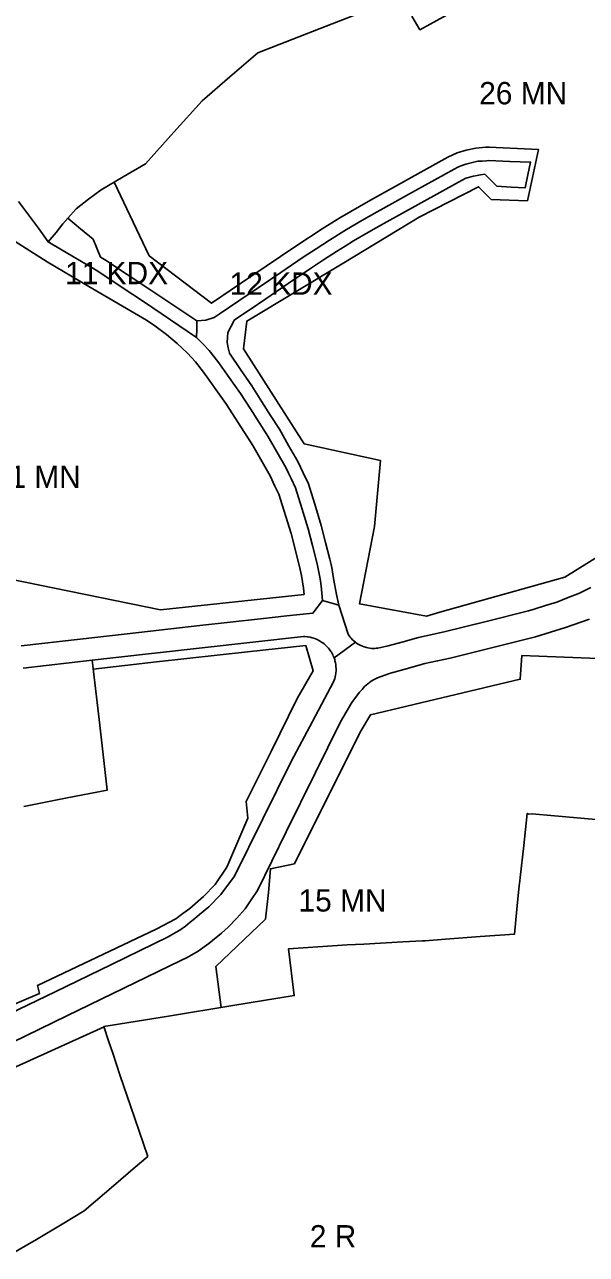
# Model space of a CAD drawing. Extents: x 7423432 to 7425824, y 5537848 to 5539677.
# Drawn here: x 7425211 to 7425463, y 5538662 to 5539213 of the extents above; entities that cross this region are included whole.
import ezdxf

# ---------------------------------------------------------------- set-up
doc = ezdxf.new("R2010")
doc.units = 0
for name, color, linetype in [('linie_rozgraniczajace', 7, 'Continuous'), ('linie_zabudowy_nieprzekraczalne', 7, 'Continuous'), ('oznaczenia_przeznaczen', 7, 'Continuous')]:
    doc.layers.add(name, color=color, linetype=linetype)

msp = doc.modelspace()

# ---------------------------------------------------------------- linework, layer by layer
at = {"layer": 'linie_rozgraniczajace'}
for points in [[(7425371.35, 5539221.95), (7425343.4, 5539211.07), (7425315.44, 5539200.19), (7425302.99, 5539189.48), (7425290.54, 5539178.76), (7425277.84, 5539164.59), (7425265.13, 5539150.42), (7425255.24, 5539144.66), (7425245.36, 5539138.9), (7425239.75, 5539134.64), (7425234.14, 5539130.39), (7425230.38, 5539126.15), (7425228.2, 5539123.69), (7425225.18, 5539119.76), (7425221.59, 5539115.58), (7425217.25, 5539121.7), (7425212.82, 5539127.69), (7425208.39, 5539133.68)], [(7425230.38, 5539126.15), (7425234.14, 5539130.39), (7425239.75, 5539134.64), (7425245.36, 5539138.9), (7425255.24, 5539144.66), (7425265.13, 5539150.42), (7425277.84, 5539164.59), (7425290.54, 5539178.76), (7425302.99, 5539189.48), (7425315.44, 5539200.19), (7425343.4, 5539211.07), (7425371.35, 5539221.95)], [(7425384.41, 5539216.52), (7425388.03, 5539210.53), (7425400.21, 5539217.11)], [(7425400.21, 5539217.11), (7425388.03, 5539210.53), (7425384.41, 5539216.52)], [(7425418.91, 5539151.93), (7425417.8, 5539151.9), (7425415.87, 5539151.76), (7425413.93, 5539151.62), (7425412.1, 5539151.2), (7425408.54, 5539150.29), (7425406.81, 5539149.8), (7425405.05, 5539148.96), (7425403.3, 5539148.12), (7425386.09, 5539138.56), (7425368.88, 5539129), (7425362.03, 5539125.07), (7425355.19, 5539121.15), (7425347.5, 5539116.34), (7425341.61, 5539112.52), (7425335.73, 5539108.7), (7425325.7, 5539101.88), (7425315.67, 5539095.07), (7425306.9, 5539089.11), (7425298.13, 5539083.14), (7425295.98, 5539081.68), (7425292.19, 5539080.59), (7425288.16, 5539080.16), (7425267.53, 5539093.92), (7425246.9, 5539107.68), (7425245.11, 5539108.69), (7425241.79, 5539116.75), (7425236.09, 5539121.45), (7425230.38, 5539126.15)], [(7425288.09, 5539072.74), (7425288.13, 5539076.45), (7425288.16, 5539080.16), (7425292.19, 5539080.59), (7425295.98, 5539081.68), (7425298.13, 5539083.14), (7425306.9, 5539089.11), (7425315.67, 5539095.07), (7425325.7, 5539101.88), (7425335.73, 5539108.7), (7425341.61, 5539112.52), (7425347.5, 5539116.34), (7425355.19, 5539121.15), (7425362.03, 5539125.07), (7425368.88, 5539129), (7425386.09, 5539138.56), (7425403.3, 5539148.12), (7425405.05, 5539148.96), (7425406.81, 5539149.8), (7425408.54, 5539150.29), (7425412.1, 5539151.2), (7425413.93, 5539151.62), (7425415.87, 5539151.76), (7425417.8, 5539151.9), (7425418.91, 5539151.93), (7425428.23, 5539151.6), (7425437.55, 5539151.28), (7425436.35, 5539145.52), (7425435.15, 5539139.76), (7425428.8, 5539140.11), (7425422.45, 5539140.46), (7425420.05, 5539142.86), (7425417.11, 5539145.82), (7425415.18, 5539145.64), (7425413.62, 5539145.32), (7425412.06, 5539145), (7425408.61, 5539144.01), (7425405.23, 5539142.3), (7425388.51, 5539133.03), (7425371.79, 5539123.75), (7425365.03, 5539119.88), (7425358.27, 5539116), (7425354.5, 5539113.64), (7425350.72, 5539111.28), (7425344.86, 5539107.47), (7425338.99, 5539103.67), (7425329.02, 5539096.89), (7425319.04, 5539090.11), (7425312.06, 5539085.37), (7425305.09, 5539080.63), (7425302.1, 5539075.02), (7425301.73, 5539070.48), (7425302.26, 5539068.14), (7425302.78, 5539065.79), (7425307.75, 5539058.45), (7425312.72, 5539051.1), (7425314.98, 5539047.57), (7425317.24, 5539044.03), (7425321.19, 5539037.86), (7425325.15, 5539031.69), (7425329.27, 5539024.49), (7425333.39, 5539017.3), (7425334.58, 5539014.78), (7425335.77, 5539012.27), (7425336.86, 5539009.98), (7425337.94, 5539007.69), (7425340.91, 5538998.18), (7425343.87, 5538988.67), (7425345.8, 5538981.08), (7425347.73, 5538973.5), (7425348.23, 5538971.2), (7425348.73, 5538968.89), (7425349.24, 5538965.74), (7425349.76, 5538962.58), (7425350.7, 5538957.77), (7425351.65, 5538952.97), (7425344.41, 5538955.04), (7425344.12, 5538958.35), (7425343.83, 5538961.65), (7425343.33, 5538964.71), (7425342.83, 5538967.77), (7425342.36, 5538969.95), (7425341.89, 5538972.13), (7425339.97, 5538979.66), (7425338.06, 5538987.19), (7425335.2, 5538996.35), (7425332.34, 5539005.5), (7425330.35, 5539009.7), (7425329.21, 5539012.11), (7425328.07, 5539014.52), (7425324.04, 5539021.55), (7425320.01, 5539028.58), (7425316.1, 5539034.69), (7425312.19, 5539040.8), (7425309.97, 5539044.27), (7425307.75, 5539047.74), (7425302.66, 5539054.85), (7425297.57, 5539061.97), (7425293.76, 5539067.01)], [(7425464.55, 5538960.86), (7425459.47, 5538958.37), (7425454.4, 5538956.38), (7425449.33, 5538954.39), (7425444.22, 5538952.81), (7425439.11, 5538951.23), (7425436.57, 5538950.44), (7425417.68, 5538945.72), (7425398.8, 5538940.99), (7425387.31, 5538938.48), (7425380.54, 5538936.63), (7425373.76, 5538934.77), (7425369.25, 5538933.77), (7425368.46, 5538933.68), (7425367.8, 5538933.63), (7425367.21, 5538933.62), (7425366.3, 5538933.65), (7425365.63, 5538933.72), (7425364.72, 5538933.86), (7425364.04, 5538934.01), (7425363.07, 5538934.29), (7425362.34, 5538934.56), (7425361.61, 5538934.87), (7425360.91, 5538935.22), (7425360.13, 5538935.68), (7425359.52, 5538936.09), (7425359.14, 5538936.37), (7425358.44, 5538936.95), (7425357.88, 5538937.47), (7425357.25, 5538938.15), (7425356.81, 5538938.67), (7425356.39, 5538939.22), (7425355.88, 5538940), (7425351.65, 5538952.97), (7425350.7, 5538957.77), (7425349.76, 5538962.58), (7425349.24, 5538965.74), (7425348.73, 5538968.89), (7425348.23, 5538971.2), (7425347.73, 5538973.5), (7425345.8, 5538981.08), (7425343.87, 5538988.67), (7425340.91, 5538998.18), (7425337.94, 5539007.69), (7425336.86, 5539009.98), (7425335.77, 5539012.27), (7425334.58, 5539014.78), (7425333.39, 5539017.3), (7425329.27, 5539024.49), (7425325.15, 5539031.69), (7425321.19, 5539037.86), (7425317.24, 5539044.03), (7425314.98, 5539047.57), (7425312.72, 5539051.1), (7425307.75, 5539058.45), (7425302.78, 5539065.79), (7425302.26, 5539068.14), (7425301.73, 5539070.48), (7425302.1, 5539075.02), (7425305.09, 5539080.63), (7425312.06, 5539085.37), (7425319.04, 5539090.11), (7425329.02, 5539096.89), (7425338.99, 5539103.67), (7425344.86, 5539107.47), (7425350.72, 5539111.28), (7425354.5, 5539113.64), (7425358.27, 5539116), (7425365.03, 5539119.88), (7425371.79, 5539123.75), (7425388.51, 5539133.03), (7425405.23, 5539142.3), (7425408.61, 5539144.01), (7425412.06, 5539145), (7425413.62, 5539145.32), (7425415.18, 5539145.64), (7425417.11, 5539145.82), (7425420.05, 5539142.86), (7425422.45, 5539140.46), (7425428.8, 5539140.11), (7425435.15, 5539139.76), (7425436.35, 5539145.52), (7425437.55, 5539151.28), (7425428.23, 5539151.6), (7425418.91, 5539151.93)], [(7425208.39, 5539133.68), (7425212.82, 5539127.69), (7425217.25, 5539121.7), (7425221.59, 5539115.58), (7425227.89, 5539111.88), (7425239.03, 5539105.34), (7425243.87, 5539102.5), (7425254.32, 5539095.51), (7425264.78, 5539088.53), (7425276.43, 5539080.63), (7425288.09, 5539072.74), (7425290.92, 5539069.88), (7425293.76, 5539067.01), (7425297.57, 5539061.97), (7425302.66, 5539054.85), (7425307.75, 5539047.74), (7425309.97, 5539044.27), (7425312.19, 5539040.8), (7425316.1, 5539034.69), (7425320.01, 5539028.58), (7425324.04, 5539021.55), (7425328.07, 5539014.52), (7425329.21, 5539012.11), (7425330.35, 5539009.7), (7425332.34, 5539005.5), (7425335.2, 5538996.35), (7425338.06, 5538987.19), (7425339.97, 5538979.66), (7425341.89, 5538972.13), (7425342.36, 5538969.95), (7425342.83, 5538967.77), (7425343.33, 5538964.71), (7425343.83, 5538961.65), (7425344.12, 5538958.35), (7425344.41, 5538955.04), (7425340.12, 5538949.43), (7425328.43, 5538948.16), (7425316.74, 5538946.9), (7425289.5, 5538943.82), (7425262.26, 5538940.75), (7425235.92, 5538937.77), (7425209.58, 5538934.8)], [(7425293.76, 5539067.01), (7425290.92, 5539069.88), (7425288.09, 5539072.74)], [(7425280.51, 5538807.61), (7425283.16, 5538809.39), (7425285.18, 5538811.05), (7425287.31, 5538812.8), (7425289.37, 5538814.56), (7425293.47, 5538818.05), (7425298.87, 5538823.46), (7425305, 5538831.65), (7425317.69, 5538857.37), (7425330.39, 5538883.09), (7425339.89, 5538900.85), (7425349.38, 5538918.62), (7425349.87, 5538920.19), (7425350.04, 5538920.81), (7425350.26, 5538921.8), (7425350.35, 5538922.37), (7425350.41, 5538922.89), (7425350.46, 5538923.46), (7425350.48, 5538924.02), (7425350.49, 5538924.67), (7425350.45, 5538925.38), (7425350.39, 5538926.03), (7425350.32, 5538926.6), (7425350.23, 5538927.11), (7425350.13, 5538927.59), (7425349.99, 5538928.14), (7425349.86, 5538928.61), (7425349.61, 5538929.35), (7425359.14, 5538936.37), (7425359.52, 5538936.09), (7425360.13, 5538935.68), (7425360.91, 5538935.22), (7425361.61, 5538934.87), (7425362.34, 5538934.56), (7425363.07, 5538934.29), (7425364.04, 5538934.01), (7425364.72, 5538933.86), (7425365.63, 5538933.72), (7425366.3, 5538933.65), (7425367.21, 5538933.62), (7425367.8, 5538933.63), (7425368.46, 5538933.68), (7425369.25, 5538933.77), (7425373.76, 5538934.77), (7425380.54, 5538936.63), (7425387.31, 5538938.48), (7425398.8, 5538940.99), (7425417.68, 5538945.72), (7425436.57, 5538950.44), (7425439.11, 5538951.23), (7425444.22, 5538952.81), (7425449.33, 5538954.39), (7425454.4, 5538956.38), (7425459.47, 5538958.37), (7425464.55, 5538960.86)], [(7425209.58, 5538934.8), (7425235.92, 5538937.77), (7425262.26, 5538940.75), (7425289.5, 5538943.82), (7425316.74, 5538946.9), (7425328.43, 5538948.16), (7425340.12, 5538949.43), (7425344.41, 5538955.04), (7425351.65, 5538952.97), (7425355.88, 5538940), (7425356.39, 5538939.22), (7425356.81, 5538938.67), (7425357.25, 5538938.15), (7425357.88, 5538937.47), (7425358.44, 5538936.95), (7425359.14, 5538936.37), (7425349.61, 5538929.35), (7425349.44, 5538929.79), (7425349.26, 5538930.22), (7425348.99, 5538930.8), (7425348.74, 5538931.28), (7425348.39, 5538931.89), (7425348.18, 5538932.24), (7425347.58, 5538933.09), (7425347.04, 5538933.77), (7425346.42, 5538934.46), (7425345.73, 5538935.13), (7425345.16, 5538935.62), (7425344.55, 5538936.09), (7425343.98, 5538936.48), (7425343.03, 5538937.06), (7425341.97, 5538937.6), (7425341.21, 5538937.92), (7425340.47, 5538938.18), (7425339.76, 5538938.39), (7425338.82, 5538938.61), (7425338.06, 5538938.75), (7425337.48, 5538938.82), (7425336.57, 5538938.89), (7425335.85, 5538938.9), (7425313.23, 5538936.39), (7425290.61, 5538933.88), (7425250.55, 5538929.36), (7425241.35, 5538928.32), (7425210.49, 5538924.84)], [(7425205.76, 5538757.48), (7425229.98, 5538769.16), (7425255.51, 5538781.54), (7425281.03, 5538793.93), (7425283.92, 5538795.37), (7425288.84, 5538798.14), (7425293.5, 5538801.54), (7425299.16, 5538806.21), (7425302.19, 5538808.81), (7425306.01, 5538812.92), (7425309.83, 5538817.03), (7425312.55, 5538821.18), (7425315.27, 5538825.34), (7425328.21, 5538851.56), (7425341.15, 5538877.78), (7425346.83, 5538889.29), (7425352.52, 5538900.8), (7425357.47, 5538909.36), (7425360.95, 5538914.02), (7425362.11, 5538915.27), (7425363.26, 5538916.52), (7425364.72, 5538917.76), (7425366.18, 5538918.99), (7425367.59, 5538919.71), (7425369, 5538920.44), (7425371.89, 5538921.46), (7425374.79, 5538922.49), (7425382.51, 5538924.66), (7425390.22, 5538926.84), (7425395.88, 5538928.07), (7425401.54, 5538929.31), (7425420.67, 5538934.1), (7425439.8, 5538938.88), (7425453.09, 5538943), (7425463.88, 5538946.77)], [(7425463.88, 5538946.77), (7425453.09, 5538943), (7425439.8, 5538938.88), (7425420.67, 5538934.1), (7425401.54, 5538929.31), (7425395.88, 5538928.07), (7425390.22, 5538926.84), (7425382.51, 5538924.66), (7425374.79, 5538922.49), (7425371.89, 5538921.46), (7425369, 5538920.44), (7425367.59, 5538919.71), (7425366.18, 5538918.99), (7425364.72, 5538917.76), (7425363.26, 5538916.52), (7425362.11, 5538915.27), (7425360.95, 5538914.02), (7425357.47, 5538909.36), (7425352.52, 5538900.8), (7425346.83, 5538889.29), (7425341.15, 5538877.78), (7425328.21, 5538851.56), (7425315.27, 5538825.34), (7425312.55, 5538821.18), (7425309.83, 5538817.03), (7425306.01, 5538812.92), (7425302.19, 5538808.81), (7425299.16, 5538806.21), (7425293.5, 5538801.54), (7425288.84, 5538798.14), (7425283.92, 5538795.37), (7425281.03, 5538793.93), (7425255.51, 5538781.54), (7425229.98, 5538769.16), (7425205.76, 5538757.48)], [(7425210.81, 5538862.9), (7425229.46, 5538866.56), (7425248.11, 5538870.22), (7425244.73, 5538899.27), (7425241.35, 5538928.32), (7425250.55, 5538929.36), (7425290.61, 5538933.88), (7425313.23, 5538936.39), (7425335.85, 5538938.9), (7425336.57, 5538938.89), (7425337.48, 5538938.82), (7425338.06, 5538938.75), (7425338.82, 5538938.61), (7425339.76, 5538938.39), (7425340.47, 5538938.18), (7425341.21, 5538937.92), (7425341.97, 5538937.6), (7425343.03, 5538937.06), (7425343.98, 5538936.48), (7425344.55, 5538936.09), (7425345.16, 5538935.62), (7425345.73, 5538935.13), (7425346.42, 5538934.46), (7425347.04, 5538933.77), (7425347.58, 5538933.09), (7425348.18, 5538932.24), (7425348.39, 5538931.89), (7425348.74, 5538931.28), (7425348.99, 5538930.8), (7425349.26, 5538930.22), (7425349.44, 5538929.79), (7425349.61, 5538929.35), (7425349.86, 5538928.61), (7425349.99, 5538928.14), (7425350.13, 5538927.59), (7425350.23, 5538927.11), (7425350.32, 5538926.6), (7425350.39, 5538926.03), (7425350.45, 5538925.38), (7425350.49, 5538924.67), (7425350.48, 5538924.02), (7425350.46, 5538923.46), (7425350.41, 5538922.89), (7425350.35, 5538922.37), (7425350.26, 5538921.8), (7425350.04, 5538920.81), (7425349.87, 5538920.19), (7425349.38, 5538918.62), (7425339.89, 5538900.85), (7425330.39, 5538883.09), (7425317.69, 5538857.37), (7425305, 5538831.65), (7425298.87, 5538823.46), (7425293.47, 5538818.05), (7425289.37, 5538814.56), (7425287.31, 5538812.8), (7425285.18, 5538811.05), (7425283.16, 5538809.39), (7425280.51, 5538807.61), (7425277.91, 5538806.05), (7425275.31, 5538804.49), (7425250.03, 5538792.23), (7425224.76, 5538779.96), (7425200.54, 5538768.29)], [(7425210.49, 5538924.84), (7425241.35, 5538928.32), (7425244.73, 5538899.27), (7425248.11, 5538870.22), (7425229.46, 5538866.56), (7425210.81, 5538862.9)], [(7425490.1, 5538855.01), (7425444.97, 5538858.95), (7425441.59, 5538859.25), (7425438.21, 5538859.56), (7425436.74, 5538859.47), (7425436.07, 5538859.75), (7425434.45, 5538845.43), (7425432.83, 5538831.12), (7425432.66, 5538829.62), (7425432.52, 5538828.46), (7425432.42, 5538827.46), (7425431.42, 5538816.97), (7425430.35, 5538805.82), (7425414.9, 5538804.65), (7425399.44, 5538803.49), (7425390.4, 5538802.81), (7425389.21, 5538802.75), (7425380.43, 5538802.27), (7425362.96, 5538801.33), (7425355.47, 5538800.93), (7425342.37, 5538800.07), (7425329.26, 5538799.21), (7425331.8, 5538778.23), (7425318.05, 5538776.03), (7425304.29, 5538773.83), (7425275.42, 5538769.09), (7425246.55, 5538764.35), (7425248.83, 5538757.5), (7425250.51, 5538752.48), (7425252.17, 5538747.43), (7425253.84, 5538742.38), (7425258.44, 5538728.92), (7425266.24, 5538706.3), (7425259.68, 5538700.66), (7425251.98, 5538694.04), (7425237.76, 5538681.92), (7425227.12, 5538675.44), (7425216.49, 5538669.05), (7425204.79, 5538662.43)], [(7425204.79, 5538662.43), (7425216.49, 5538669.05), (7425227.12, 5538675.44), (7425237.76, 5538681.92), (7425251.98, 5538694.04), (7425259.68, 5538700.66), (7425266.24, 5538706.3), (7425258.44, 5538728.92), (7425253.84, 5538742.38), (7425252.17, 5538747.43), (7425250.51, 5538752.48), (7425248.83, 5538757.5), (7425246.55, 5538764.35), (7425275.42, 5538769.09), (7425304.29, 5538773.83), (7425318.05, 5538776.03), (7425331.8, 5538778.23), (7425329.26, 5538799.21), (7425342.37, 5538800.07), (7425355.47, 5538800.93), (7425362.96, 5538801.33), (7425380.43, 5538802.27), (7425389.21, 5538802.75), (7425390.4, 5538802.81), (7425399.44, 5538803.49), (7425414.9, 5538804.65), (7425430.35, 5538805.82), (7425431.42, 5538816.97), (7425432.42, 5538827.46), (7425432.52, 5538828.46), (7425432.66, 5538829.62), (7425432.83, 5538831.12), (7425434.45, 5538845.43), (7425436.07, 5538859.75), (7425436.74, 5538859.47), (7425438.21, 5538859.56), (7425441.59, 5538859.25), (7425444.97, 5538858.95), (7425490.1, 5538855.01)], [(7425200.54, 5538768.29), (7425224.76, 5538779.96), (7425250.03, 5538792.23), (7425275.31, 5538804.49), (7425277.91, 5538806.05), (7425280.51, 5538807.61)]]:
    msp.add_lwpolyline(points, dxfattribs=at)
msp.add_lwpolyline([(7425221.59, 5539115.58), (7425225.18, 5539119.76), (7425228.2, 5539123.69), (7425230.38, 5539126.15), (7425236.09, 5539121.45), (7425241.79, 5539116.75), (7425245.11, 5539108.69), (7425246.9, 5539107.68), (7425267.53, 5539093.92), (7425288.16, 5539080.16), (7425288.13, 5539076.45), (7425288.09, 5539072.74), (7425276.43, 5539080.63), (7425264.78, 5539088.53), (7425254.32, 5539095.51), (7425243.87, 5539102.5), (7425239.03, 5539105.34), (7425227.89, 5539111.88)], close=True, dxfattribs=at)
at = {"layer": 'linie_zabudowy_nieprzekraczalne'}
for points in [[(7425251.25, 5539142.33), (7425266.85, 5539109.33), (7425294.76, 5539088.11), (7425294.76, 5539088.11), (7425312.3, 5539100.03), (7425332.41, 5539113.7), (7425344.27, 5539121.4), (7425352.1, 5539126.29), (7425365.93, 5539134.22), (7425400.54, 5539153.46), (7425404.68, 5539155.43), (7425408.77, 5539156.6), (7425413.05, 5539157.57), (7425417.5, 5539157.9), (7425418.94, 5539157.93), (7425441.1, 5539156.89), (7425436.15, 5539134), (7425419.83, 5539134.59), (7425414.28, 5539140.24), (7425414.28, 5539140.24), (7425414.28, 5539140.24), (7425414.28, 5539140.24), (7425387.66, 5539126.58), (7425387.66, 5539126.58), (7425353.94, 5539106.22), (7425310.53, 5539080.12), (7425310.53, 5539080.12), (7425310.53, 5539080.12), (7425309.09, 5539067.76), (7425336.17, 5539025.2), (7425336.17, 5539025.2), (7425370.37, 5539017.71), (7425367.7, 5538988.14), (7425360.97, 5538953.62), (7425391.02, 5538948.07), (7425396.95, 5538949.86), (7425452.92, 5538965.48), (7425476.15, 5538979.97)], [(7425129.52, 5538980.01), (7425271.97, 5538950.91), (7425336.15, 5538957.82), (7425335.89, 5538960.66), (7425334.97, 5538966.27), (7425334.1, 5538970.29), (7425330.36, 5538985.01), (7425324.87, 5539002.59), (7425323.12, 5539006.27), (7425320.97, 5539010.81), (7425313.17, 5539024.43), (7425305.45, 5539036.49), (7425301.12, 5539043.26), (7425291.13, 5539057.23), (7425287.6, 5539061.89), (7425283.99, 5539065.83), (7425279.44, 5539070.05), (7425274.58, 5539074.12), (7425269.4, 5539077.94), (7425265.68, 5539080.48), (7425239.83, 5539095.6), (7425221.12, 5539106.58), (7425200.75, 5539119.54)], [(7425336.98, 5538935), (7425310.92, 5538932.11), (7425270.19, 5538927.55), (7425241.8, 5538924.35)], [(7425505.77, 5538927.55), (7425433.63, 5538930.47), (7425432.93, 5538919.83), (7425432.93, 5538919.83), (7425432.93, 5538919.83), (7425432.93, 5538919.83), (7425365.83, 5538903.84), (7425365.83, 5538903.84), (7425365.83, 5538903.84), (7425365.83, 5538903.84), (7425365.83, 5538903.84), (7425361.34, 5538896.08), (7425331.82, 5538837.18), (7425321.13, 5538834.99), (7425320.24, 5538824.41), (7425318.89, 5538812.52), (7425318.89, 5538812.52), (7425296.71, 5538791.34), (7425296.71, 5538791.34), (7425299.04, 5538772.97)], [(7425301.59, 5538835.77), (7425311.01, 5538857.67), (7425310.32, 5538865.14), (7425321.43, 5538887.51), (7425333.11, 5538911.19), (7425340.31, 5538923.58), (7425336.98, 5538935)], [(7425217.71, 5538779.25), (7425216.8, 5538782.74), (7425269.93, 5538808), (7425278.73, 5538812.67), (7425281.86, 5538815.05), (7425284.98, 5538817.3), (7425291.21, 5538822.66), (7425296.37, 5538827.94), (7425301.59, 5538835.77)], [(7425099.35, 5538732.38), (7425120.62, 5538737.92), (7425217.71, 5538779.25)], [(7425246.74, 5538764.34), (7425205.52, 5538745.6), (7425203.52, 5538750.99), (7425189.77, 5538745.41), (7425191.8, 5538740.54), (7425095.22, 5538695.24)]]:
    msp.add_lwpolyline(points, dxfattribs=at)

# ---------------------------------------------------------------- texts
at = {"layer": 'oznaczenia_przeznaczen'}
for s, p in [('26 MN', (7425414.54, 5539177.12)), ('11 KDX', (7425229.21, 5539096.62)), ('12 KDX', (7425302.84, 5539091.89)), ('31 MN', (7425196.84, 5539005.48)), ('15 MN', (7425333.69, 5538815.87)), ('2 R', (7425338.73, 5538665.53))]:
    msp.add_text(s, height=10, dxfattribs=at).set_placement(p)

doc.saveas('drawing.dxf')
